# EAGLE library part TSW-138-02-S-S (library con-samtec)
THROUGH-HOLE .025" SQ POST HEADER Source: Samtec TSW.pdf
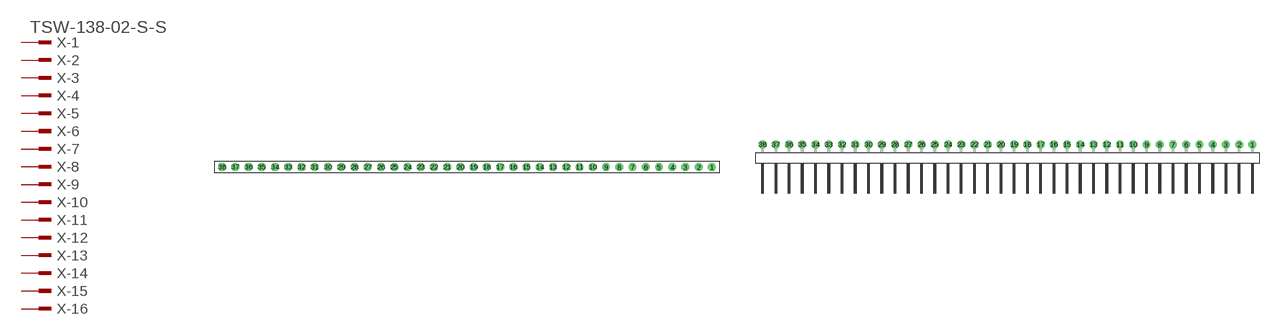
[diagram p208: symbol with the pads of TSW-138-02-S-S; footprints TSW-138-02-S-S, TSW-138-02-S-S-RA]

Designator prefix X; gates -1=MPINV -2=MPIN -3=MPIN -4=MPIN -5=MPIN -6=MPIN -7=MPIN -8=MPIN -9=MPIN -10=MPIN -11=MPIN -12=MPIN -13=MPIN -14=MPIN -15=MPIN -16=MPIN -17=MPIN -18=MPIN -19=MPIN -20=MPIN -21=MPIN -22=MPIN -23=MPIN -24=MPIN -25=MPIN -26=MPIN -27=MPIN -28=MPIN -29=MPIN -30=MPIN -31=MPIN -32=MPIN -33=MPIN -34=MPIN -35=MPIN -36=MPIN -37=MPIN -38=MPIN

## TSW-138-02-S-S (OC_FARNELL: unknown; OC_NEWARK: unknown)  [TSW-138-02-S-S]
1  -1:1  pas
2  -2:1  pas
3  -3:1  pas
4  -4:1  pas
5  -5:1  pas
6  -6:1  pas
7  -7:1  pas
8  -8:1  pas
9  -9:1  pas
10  -10:1  pas
11  -11:1  pas
12  -12:1  pas
13  -13:1  pas
14  -14:1  pas
15  -15:1  pas
16  -16:1  pas
17  -17:1  pas
18  -18:1  pas
19  -19:1  pas
20  -20:1  pas
21  -21:1  pas
22  -22:1  pas
23  -23:1  pas
24  -24:1  pas
25  -25:1  pas
26  -26:1  pas
27  -27:1  pas
28  -28:1  pas
29  -29:1  pas
30  -30:1  pas
31  -31:1  pas
32  -32:1  pas
33  -33:1  pas
34  -34:1  pas
35  -35:1  pas
36  -36:1  pas
37  -37:1  pas
38  -38:1  pas

## TSW-138-02-S-S-RA (OC_FARNELL: unknown; OC_NEWARK: unknown)  [TSW-138-02-S-S-RA]
Pads as for TSW-138-02-S-S

## Footprint TSW-138-02-S-S (pad centres in mm)
THROUGH-HOLE .025" SQ POST HEADER Source: Samtec TSW.pdf
drill 1 pad 1.5 octagon: 1 46.99,0; 2 44.45,0; 3 41.91,0; 4 39.37,0; 5 36.83,0; 6 34.29,0; 7 31.75,0; 8 29.21,0; 9 26.67,0; 10 24.13,0; 11 21.59,0; 12 19.05,0; 13 16.51,0; 14 13.97,0; 15 11.43,0; 16 8.89,0; 17 6.35,0; 18 3.81,0; 19 1.27,0; 20 -1.27,0; 21 -3.81,0; 22 -6.35,0; 23 -8.89,0; 24 -11.43,0; 25 -13.97,0; 26 -16.51,0; 27 -19.05,0; 28 -21.59,0; 29 -24.13,0; 30 -26.67,0; 31 -29.21,0; 32 -31.75,0; 33 -34.29,0; 34 -36.83,0; 35 -39.37,0; 36 -41.91,0; 37 -44.45,0; 38 -46.99,0

## Footprint TSW-138-02-S-S-RA (pad centres in mm)
THROUGH-HOLE .025" SQ POST HEADER Source: Samtec TSW.pdf
drill 1 pad 1.5 octagon: 1 46.99,1.524; 2 44.45,1.524; 3 41.91,1.524; 4 39.37,1.524; 5 36.83,1.524; 6 34.29,1.524; 7 31.75,1.524; 8 29.21,1.524; 9 26.67,1.524; 10 24.13,1.524; 11 21.59,1.524; 12 19.05,1.524; 13 16.51,1.524; 14 13.97,1.524; 15 11.43,1.524; 16 8.89,1.524; 17 6.35,1.524; 18 3.81,1.524; 19 1.27,1.524; 20 -1.27,1.524; 21 -3.81,1.524; 22 -6.35,1.524; 23 -8.89,1.524; 24 -11.43,1.524; 25 -13.97,1.524; 26 -16.51,1.524; 27 -19.05,1.524; 28 -21.59,1.524; 29 -24.13,1.524; 30 -26.67,1.524; 31 -29.21,1.524; 32 -31.75,1.524; 33 -34.29,1.524; 34 -36.83,1.524; 35 -39.37,1.524; 36 -41.91,1.524; 37 -44.45,1.524; 38 -46.99,1.524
